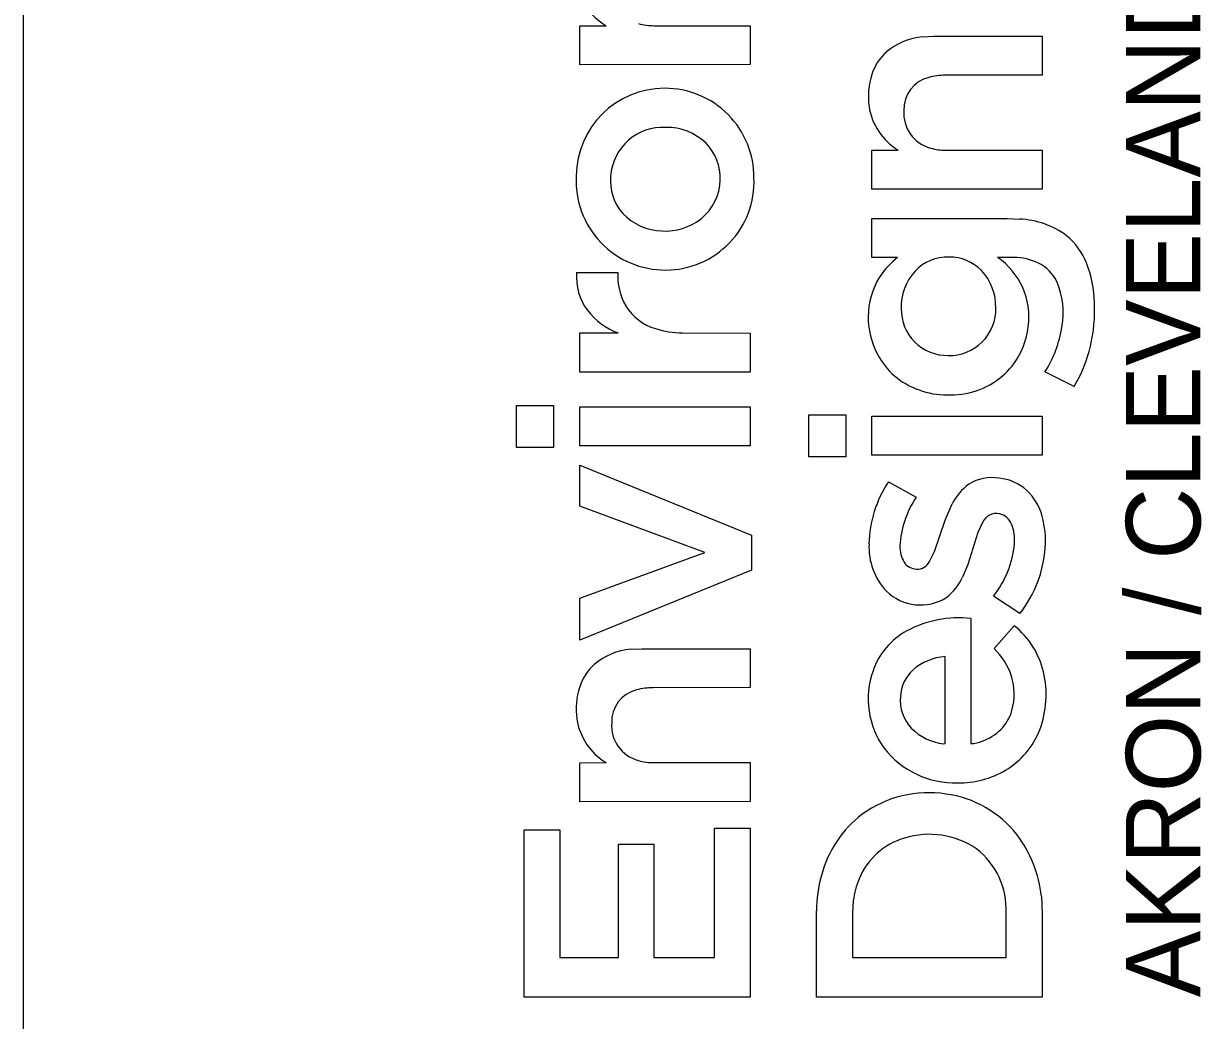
# Model space of a CAD drawing. Extents: x -0.5 to 34, y 0 to 22.
# Drawn here: x 32 to 32.901, y 3.12 to 3.882 of the extents above; entities that cross this region are included whole.
import ezdxf

# ---------------------------------------------------------------- set-up
doc = ezdxf.new("R2010")
doc.units = 0
doc.layers.add('SV_X_Mon_Cells_Found', color=7, linetype='Continuous')
doc.layers.add('SV_X_Shot_Marker', color=7, linetype='Continuous')

msp = doc.modelspace()

# ---------------------------------------------------------------- linework, layer by layer
at = {"layer": 'SV_X_Mon_Cells_Found'}
for p, q in [((32.42542, 3.88066), (32.44552, 3.88071)), ((32.42542, 3.85086), (32.42542, 3.88066)), ((32.48222, 3.88071), (32.55569, 3.88071)), ((32.55569, 3.88071), (32.55571, 3.85096)), ((32.68784, 3.8722), (32.69634, 3.87266)), ((32.69634, 3.87266), (32.77916, 3.87266)), ((32.77916, 3.87266), (32.77917, 3.84287)), ((32.55571, 3.85096), (32.42542, 3.85086)), ((32.77917, 3.84287), (32.70485, 3.8428)), ((32.64888, 3.7855), (32.66897, 3.78555)), ((32.64888, 3.75569), (32.64888, 3.7855)), ((32.70568, 3.78555), (32.77915, 3.78555)), ((32.77915, 3.78555), (32.77917, 3.75579)), ((32.77917, 3.75579), (32.64888, 3.75569)), ((32.6489, 3.70336), (32.64889, 3.73322)), ((32.64889, 3.73322), (32.75236, 3.73322)), ((32.75236, 3.73322), (32.76191, 3.73285)), ((32.66836, 3.70336), (32.6489, 3.70336)), ((32.75763, 3.70356), (32.74487, 3.70361)), ((32.42299, 3.69193), (32.45454, 3.69193)), ((32.42542, 3.64577), (32.45473, 3.64579)), ((32.42542, 3.61593), (32.42542, 3.64577)), ((32.50413, 3.64581), (32.55571, 3.64573)), ((32.55571, 3.64573), (32.55565, 3.61593)), ((32.55565, 3.61593), (32.42542, 3.61593)), ((32.8036, 3.60491), (32.7812, 3.61598)), ((32.37705, 3.55818), (32.37705, 3.59026)), ((32.37705, 3.59026), (32.40543, 3.59026)), ((32.40543, 3.59026), (32.40543, 3.55818)), ((32.42542, 3.55942), (32.42542, 3.58928)), ((32.42542, 3.58928), (32.55571, 3.58928)), ((32.55571, 3.58928), (32.55571, 3.55942)), ((32.60051, 3.55111), (32.60051, 3.58319)), ((32.60051, 3.58319), (32.62889, 3.58319)), ((32.62889, 3.58319), (32.62889, 3.55111)), ((32.64888, 3.55234), (32.64888, 3.5822)), ((32.64888, 3.5822), (32.77917, 3.5822)), ((32.77917, 3.5822), (32.77917, 3.55234)), ((32.55571, 3.55942), (32.42542, 3.55942)), ((32.40543, 3.55818), (32.37705, 3.55818)), ((32.62889, 3.55111), (32.60051, 3.55111)), ((32.77917, 3.55234), (32.64888, 3.55234)), ((32.42542, 3.51327), (32.42542, 3.5446)), ((32.42542, 3.5446), (32.5567, 3.4913)), ((32.66151, 3.53207), (32.68268, 3.52025)), ((32.70483, 3.50258), (32.71036, 3.51526)), ((32.52117, 3.47798), (32.42542, 3.51327)), ((32.69675, 3.47868), (32.70483, 3.50258)), ((32.73342, 3.50101), (32.72985, 3.4933)), ((32.5567, 3.4913), (32.5567, 3.46441)), ((32.72985, 3.4933), (32.72213, 3.46882)), ((32.42542, 3.44294), (32.52117, 3.47798)), ((32.69299, 3.47117), (32.69675, 3.47868)), ((32.72213, 3.46882), (32.71822, 3.45921)), ((32.5567, 3.46441), (32.42542, 3.41086)), ((32.42542, 3.41086), (32.42542, 3.44294)), ((32.76214, 3.43141), (32.74198, 3.44469)), ((32.72453, 3.42747), (32.72463, 3.33195)), ((32.74228, 3.40465), (32.75768, 3.422)), ((32.46439, 3.40397), (32.47289, 3.40443)), ((32.47289, 3.40443), (32.55571, 3.40443)), ((32.55571, 3.40443), (32.55571, 3.37465)), ((32.70489, 3.33182), (32.70489, 3.39834)), ((32.55571, 3.37465), (32.4814, 3.37457)), ((32.70361, 3.33165), (32.70489, 3.33182)), ((32.42542, 3.31728), (32.44552, 3.31733)), ((32.42542, 3.28747), (32.42542, 3.31728)), ((32.48222, 3.31733), (32.55569, 3.31733)), ((32.55569, 3.31733), (32.55571, 3.28756)), ((32.55571, 3.28756), (32.42542, 3.28747)), ((32.38298, 3.13791), (32.38298, 3.26598)), ((32.38298, 3.26598), (32.41012, 3.26598)), ((32.41012, 3.26598), (32.41012, 3.16827)), ((32.52857, 3.16827), (32.52857, 3.26722)), ((32.52857, 3.26722), (32.55571, 3.26722)), ((32.55571, 3.26722), (32.55571, 3.13791)), ((32.45503, 3.16827), (32.45503, 3.25488)), ((32.45503, 3.25488), (32.48218, 3.25488)), ((32.48218, 3.25488), (32.48218, 3.16827)), ((32.63465, 3.21178), (32.63407, 3.2023)), ((32.77847, 3.21497), (32.77917, 3.2021)), ((32.60643, 3.13799), (32.60644, 3.204)), ((32.63407, 3.2023), (32.63407, 3.16838)), ((32.75149, 3.16834), (32.75153, 3.20239)), ((32.77917, 3.2021), (32.77917, 3.138)), ((32.41012, 3.16827), (32.45503, 3.16827)), ((32.48218, 3.16827), (32.52857, 3.16827)), ((32.63407, 3.16838), (32.75149, 3.16834)), ((32.55571, 3.13791), (32.38298, 3.13791)), ((32.77917, 3.138), (32.60643, 3.13799))]:
    msp.add_line(p, q, dxfattribs=at)
for points in [[(32.42542, 3.85086), (32.42542, 3.88066), (32.44552, 3.88071)], [(32.48222, 3.88071), (32.55569, 3.88071), (32.55571, 3.85096), (32.42542, 3.85086)], [(32.68784, 3.8722), (32.69634, 3.87266), (32.77916, 3.87266), (32.77917, 3.84287), (32.70485, 3.8428)], [(32.64888, 3.75569), (32.64888, 3.7855), (32.66897, 3.78555)], [(32.70568, 3.78555), (32.77915, 3.78555), (32.77917, 3.75579), (32.64888, 3.75569)], [(32.66836, 3.70336), (32.6489, 3.70336), (32.64889, 3.73322), (32.75236, 3.73322), (32.76191, 3.73285)], [(32.75763, 3.70356), (32.74487, 3.70361)], [(32.42299, 3.69193), (32.45454, 3.69193)], [(32.50413, 3.64581), (32.55571, 3.64573), (32.55565, 3.61593), (32.42542, 3.61593)], [(32.42542, 3.61593), (32.42542, 3.64577), (32.45473, 3.64579)], [(32.8036, 3.60491), (32.7812, 3.61598)], [(32.66151, 3.53207), (32.68268, 3.52025)], [(32.69299, 3.47117), (32.69675, 3.47868), (32.70483, 3.50258), (32.71036, 3.51526)], [(32.73342, 3.50101), (32.72985, 3.4933), (32.72213, 3.46882), (32.71822, 3.45921)], [(32.76214, 3.43141), (32.74198, 3.44469)], [(32.72453, 3.42747), (32.72463, 3.33195)], [(32.74228, 3.40465), (32.75768, 3.422)], [(32.46439, 3.40397), (32.47289, 3.40443), (32.55571, 3.40443), (32.55571, 3.37465), (32.4814, 3.37457)], [(32.70361, 3.33165), (32.70489, 3.33182), (32.70489, 3.39834)], [(32.42542, 3.28747), (32.42542, 3.31728), (32.44552, 3.31733)], [(32.48222, 3.31733), (32.55569, 3.31733), (32.55571, 3.28756), (32.42542, 3.28747)], [(32.77847, 3.21497), (32.77917, 3.2021), (32.77917, 3.138), (32.60643, 3.13799)], [(32.63465, 3.21178), (32.63407, 3.2023), (32.63407, 3.16838), (32.75149, 3.16834), (32.75153, 3.20239)], [(32.60643, 3.13799), (32.60644, 3.204)]]:
    msp.add_lwpolyline(points, dxfattribs=at)
for points in [[(32.37705, 3.55818), (32.37705, 3.59026), (32.40543, 3.59026), (32.40543, 3.55818)], [(32.42542, 3.55942), (32.42542, 3.58928), (32.55571, 3.58928), (32.55571, 3.55942)], [(32.60051, 3.55111), (32.60051, 3.58319), (32.62889, 3.58319), (32.62889, 3.55111)], [(32.64888, 3.55234), (32.64888, 3.5822), (32.77917, 3.5822), (32.77917, 3.55234)], [(32.42542, 3.41086), (32.42542, 3.44294), (32.52117, 3.47798), (32.42542, 3.51327), (32.42542, 3.5446), (32.5567, 3.4913), (32.5567, 3.46441)], [(32.38298, 3.13791), (32.38298, 3.26598), (32.41012, 3.26598), (32.41012, 3.16827), (32.45503, 3.16827), (32.45503, 3.25488), (32.48218, 3.25488), (32.48218, 3.16827), (32.52857, 3.16827), (32.52857, 3.26722), (32.55571, 3.26722), (32.55571, 3.13791)]]:
    msp.add_lwpolyline(points, close=True, dxfattribs=at)
for centre, radius, start, end in [((32.47027, 3.92141), 0.04763, 188.96462, 238.69865), ((32.47027, 3.92141), 0.04763, 188.96462, 238.69865), ((32.48183, 3.92286), 0.04215, 254.08913, 270.52838), ((32.48183, 3.92286), 0.04215, 254.08913, 270.52838), ((32.69216, 3.82251), 0.04988, 94.97056, 130.22484), ((32.69216, 3.82251), 0.04988, 94.97056, 130.22484), ((32.68694, 3.83085), 0.04016, 132.22383, 161.68229), ((32.68694, 3.83085), 0.04016, 132.22383, 161.68229), ((32.70217, 3.82642), 0.05602, 162.27398, 187.79173), ((32.70217, 3.82642), 0.05602, 162.27398, 187.79173), ((32.69828, 3.81689), 0.02498, 103.68683, 182.21395), ((32.69828, 3.81689), 0.02498, 103.68683, 182.21395), ((32.70453, 3.79679), 0.04601, 89.60515, 105.33026), ((32.70453, 3.79679), 0.04601, 89.60515, 105.33026), ((32.49014, 3.76543), 0.0674, 89.84756, 179.64047), ((32.49014, 3.76543), 0.0674, 89.84756, 179.64047), ((32.49057, 3.76474), 0.0681, 359.54009, 90.21138), ((32.49057, 3.76474), 0.0681, 359.54009, 90.21138), ((32.69372, 3.82624), 0.04763, 188.96462, 238.69865), ((32.69372, 3.82624), 0.04763, 188.96462, 238.69865), ((32.7008, 3.81381), 0.02757, 175.58441, 255.13816), ((32.7008, 3.81381), 0.02757, 175.58441, 255.13816), ((32.48923, 3.76263), 0.0404, 87.04809, 175.57259), ((32.48923, 3.76263), 0.0404, 87.04809, 175.57259), ((32.49204, 3.75999), 0.04299, 45.84264, 90.98008), ((32.49204, 3.75999), 0.04299, 45.84264, 90.98008), ((32.49458, 3.76421), 0.03821, 357.88569, 44.15902), ((32.49458, 3.76421), 0.03821, 357.88569, 44.15902), ((32.70529, 3.82769), 0.04215, 254.08913, 270.52838), ((32.70529, 3.82769), 0.04215, 254.08913, 270.52838), ((32.49083, 3.76209), 0.06819, 176.8344, 270.40384), ((32.49083, 3.76209), 0.06819, 176.8344, 270.40384), ((32.48729, 3.7625), 0.03848, 175.15378, 221.14706), ((32.48729, 3.7625), 0.03848, 175.15378, 221.14706), ((32.49123, 3.76139), 0.06749, 270.06243, 2.37759), ((32.49123, 3.76139), 0.06749, 270.06243, 2.37759), ((32.49446, 3.76318), 0.0383, 308.28936, 359.43468), ((32.49446, 3.76318), 0.0383, 308.28936, 359.43468), ((32.48919, 3.76607), 0.04228, 223.09994, 268.80895), ((32.48919, 3.76607), 0.04228, 223.09994, 268.80895), ((32.49096, 3.7679), 0.04418, 266.56515, 308.06078), ((32.49096, 3.7679), 0.04418, 266.56515, 308.06078), ((32.75907, 3.66789), 0.06503, 53.40344, 87.49062), ((32.75907, 3.66789), 0.06503, 53.40344, 87.49062), ((32.76517, 3.68039), 0.05141, 21.60748, 50.5577), ((32.76517, 3.68039), 0.05141, 21.60748, 50.5577), ((32.70292, 3.65813), 0.05692, 127.37482, 192.22468), ((32.70292, 3.65813), 0.05692, 127.37482, 192.22468), ((32.70693, 3.66927), 0.0346, 88.47302, 136.42562), ((32.70693, 3.66927), 0.0346, 88.47302, 136.42562), ((32.70814, 3.66963), 0.03424, 44.27195, 90.47623), ((32.70814, 3.66963), 0.03424, 44.27195, 90.47623), ((32.71421, 3.65829), 0.05472, 352.1125, 55.92295), ((32.71421, 3.65829), 0.05472, 352.1125, 55.92295), ((32.75666, 3.65725), 0.04633, 65.01687, 88.8011), ((32.75666, 3.65725), 0.04633, 65.01687, 88.8011), ((32.7626, 3.67155), 0.03085, 26.26808, 63.80301), ((32.7626, 3.67155), 0.03085, 26.26808, 63.80301), ((32.73069, 3.66714), 0.08835, 1.15143, 21.3627), ((32.73069, 3.66714), 0.08835, 1.15143, 21.3627), ((32.46616, 3.68882), 0.04329, 175.87313, 216.34747), ((32.46616, 3.68882), 0.04329, 175.87313, 216.34747), ((32.50087, 3.68948), 0.04639, 176.9688, 209.60636), ((32.50087, 3.68948), 0.04639, 176.9688, 209.60636), ((32.71141, 3.66602), 0.0401, 137.46739, 182.33237), ((32.71141, 3.66602), 0.0401, 137.46739, 182.33237), ((32.70368, 3.666), 0.03996, 358.57141, 43.53765), ((32.70368, 3.666), 0.03996, 358.57141, 43.53765), ((32.73565, 3.66154), 0.05953, 349.30734, 23.43071), ((32.73565, 3.66154), 0.05953, 349.30734, 23.43071), ((32.70538, 3.66244), 0.11383, 329.6388, 3.25998), ((32.70538, 3.66244), 0.11383, 329.6388, 3.25998), ((32.47466, 3.69716), 0.05511, 218.09809, 248.7907), ((32.47466, 3.69716), 0.05511, 218.09809, 248.7907), ((32.49514, 3.68814), 0.04079, 211.94466, 253.2028), ((32.49514, 3.68814), 0.04079, 211.94466, 253.2028), ((32.70645, 3.6637), 0.03511, 178.88208, 271.08374), ((32.70645, 3.6637), 0.03511, 178.88208, 271.08374), ((32.70818, 3.66404), 0.03546, 268.27882, 1.55016), ((32.70818, 3.66404), 0.03546, 268.27882, 1.55016), ((32.50465, 3.7165), 0.07069, 252.46555, 269.57296), ((32.50465, 3.7165), 0.07069, 252.46555, 269.57296), ((32.70988, 3.65708), 0.05887, 313.74196, 353.8554), ((32.70988, 3.65708), 0.05887, 313.74196, 353.8554), ((32.70738, 3.66334), 0.08771, 327.31495, 351.57478), ((32.70738, 3.66334), 0.08771, 327.31495, 351.57478), ((32.70463, 3.65696), 0.05837, 190.75182, 231.28919), ((32.70463, 3.65696), 0.05837, 190.75182, 231.28919), ((32.70954, 3.65901), 0.06051, 269.6361, 312.70877), ((32.70954, 3.65901), 0.06051, 269.6361, 312.70877), ((32.70632, 3.66112), 0.06269, 232.46061, 272.59022), ((32.70632, 3.66112), 0.06269, 232.46061, 272.59022), ((32.73636, 3.48258), 0.08973, 146.53104, 178.7571), ((32.73636, 3.48258), 0.08973, 146.53104, 178.7571), ((32.7406, 3.5026), 0.03263, 80.17192, 122.51969), ((32.7406, 3.5026), 0.03263, 80.17192, 122.51969), ((32.74278, 3.49824), 0.03667, 47.79344, 84.68918), ((32.74278, 3.49824), 0.03667, 47.79344, 84.68918), ((32.74661, 3.49713), 0.04053, 125.51182, 153.41595), ((32.74661, 3.49713), 0.04053, 125.51182, 153.41595), ((32.73788, 3.4946), 0.04267, 14.9966, 46.20632), ((32.73788, 3.4946), 0.04267, 14.9966, 46.20632), ((32.74519, 3.4789), 0.07495, 146.51121, 176.91007), ((32.74519, 3.4789), 0.07495, 146.51121, 176.91007), ((32.74384, 3.49631), 0.01143, 76.66094, 155.7053), ((32.74384, 3.49631), 0.01143, 76.66094, 155.7053), ((32.74397, 3.49511), 0.01256, 21.5098, 78.52618), ((32.74397, 3.49511), 0.01256, 21.5098, 78.52618), ((32.71044, 3.48674), 0.07121, 355.83062, 15.39138), ((32.71044, 3.48674), 0.07121, 355.83062, 15.39138), ((32.72592, 3.48766), 0.03209, 354.57264, 22.06805), ((32.72592, 3.48766), 0.03209, 354.57264, 22.06805), ((32.69666, 3.48238), 0.05005, 177.53659, 222.79318), ((32.69666, 3.48238), 0.05005, 177.53659, 222.79318), ((32.6931, 3.48233), 0.02276, 178.47474, 211.08679), ((32.6931, 3.48233), 0.02276, 178.47474, 211.08679), ((32.68248, 3.49149), 0.0757, 321.81101, 354.79685), ((32.68248, 3.49149), 0.0757, 321.81101, 354.79685), ((32.68952, 3.4882), 0.09219, 321.9777, 355.87384), ((32.68952, 3.4882), 0.09219, 321.9777, 355.87384), ((32.68331, 3.4767), 0.01148, 212.23676, 268.37769), ((32.68331, 3.4767), 0.01148, 212.23676, 268.37769), ((32.68342, 3.47589), 0.01067, 267.71603, 333.73375), ((32.68342, 3.47589), 0.01067, 267.71603, 333.73375), ((32.68098, 3.4758), 0.04077, 308.08772, 335.98736), ((32.68098, 3.4758), 0.04077, 308.08772, 335.98736), ((32.68599, 3.47535), 0.0375, 225.98539, 302.47965), ((32.68599, 3.47535), 0.0375, 225.98539, 302.47965), ((32.7152, 3.34414), 0.08384, 83.61499, 118.28755), ((32.7152, 3.34414), 0.08384, 83.61499, 118.28755), ((32.70239, 3.36906), 0.05583, 118.83082, 160.62438), ((32.70239, 3.36906), 0.05583, 118.83082, 160.62438), ((32.71744, 3.37167), 0.06443, 13.53365, 51.36148), ((32.71744, 3.37167), 0.06443, 13.53365, 51.36148), ((32.46871, 3.35428), 0.04988, 94.96958, 130.22249), ((32.46871, 3.35428), 0.04988, 94.96958, 130.22249), ((32.70785, 3.35609), 0.04235, 94.00805, 130.88169), ((32.70785, 3.35609), 0.04235, 94.00805, 130.88169), ((32.70378, 3.36556), 0.05486, 19.03571, 45.44059), ((32.70378, 3.36556), 0.05486, 19.03571, 45.44059), ((32.46348, 3.36263), 0.04015, 132.22192, 161.68183), ((32.46348, 3.36263), 0.04015, 132.22192, 161.68183), ((32.71041, 3.36612), 0.06437, 160.52012, 215.78311), ((32.71041, 3.36612), 0.06437, 160.52012, 215.78311), ((32.70048, 3.36628), 0.02985, 132.98507, 177.179), ((32.70048, 3.36628), 0.02985, 132.98507, 177.179), ((32.71069, 3.3697), 0.047, 344.60586, 17.007), ((32.71069, 3.3697), 0.047, 344.60586, 17.007), ((32.70635, 3.36921), 0.07579, 339.3542, 13.37853), ((32.70635, 3.36921), 0.07579, 339.3542, 13.37853), ((32.47872, 3.35819), 0.05601, 162.27355, 187.79185), ((32.47872, 3.35819), 0.05601, 162.27355, 187.79185), ((32.47482, 3.34867), 0.02498, 103.68646, 182.21874), ((32.47482, 3.34867), 0.02498, 103.68646, 182.21874), ((32.48108, 3.32856), 0.04601, 89.60494, 105.3284), ((32.48108, 3.32856), 0.04601, 89.60494, 105.3284), ((32.7017, 3.36503), 0.03115, 175.00126, 223.28301), ((32.7017, 3.36503), 0.03115, 175.00126, 223.28301), ((32.7224, 3.36715), 0.03504, 288.00773, 343.55078), ((32.7224, 3.36715), 0.03504, 288.00773, 343.55078), ((32.47026, 3.35802), 0.04762, 188.96199, 238.70369), ((32.47026, 3.35802), 0.04762, 188.96199, 238.70369), ((32.47735, 3.34558), 0.02756, 175.58538, 255.14386), ((32.47735, 3.34558), 0.02756, 175.58538, 255.14386), ((32.70891, 3.37363), 0.04231, 225.06188, 262.79738), ((32.70891, 3.37363), 0.04231, 225.06188, 262.79738), ((32.71894, 3.3652), 0.0626, 300.94269, 338.73225), ((32.71894, 3.3652), 0.0626, 300.94269, 338.73225), ((32.72474, 3.35216), 0.02021, 269.7003, 294.8711), ((32.72474, 3.35216), 0.02021, 269.7003, 294.8711), ((32.71253, 3.37054), 0.06872, 217.74516, 271.65431), ((32.71253, 3.37054), 0.06872, 217.74516, 271.65431), ((32.48183, 3.35948), 0.04215, 254.09162, 270.52835), ((32.48183, 3.35948), 0.04215, 254.09162, 270.52835), ((32.71549, 3.37241), 0.07056, 269.20477, 300.33412), ((32.71549, 3.37241), 0.07056, 269.20477, 300.33412), ((32.69229, 3.20792), 0.08641, 81.19402, 125.99844), ((32.69229, 3.20792), 0.08641, 81.19402, 125.99844), ((32.69458, 3.21132), 0.08272, 37.85208, 82.40204), ((32.69458, 3.21132), 0.08272, 37.85208, 82.40204), ((32.69387, 3.20893), 0.08654, 127.23621, 165.14796), ((32.69387, 3.20893), 0.08654, 127.23621, 165.14796), ((32.69279, 3.19862), 0.06389, 55.67272, 107.20935), ((32.69279, 3.19862), 0.06389, 55.67272, 107.20935), ((32.68586, 3.20567), 0.09308, 5.73329, 37.30396), ((32.68586, 3.20567), 0.09308, 5.73329, 37.30396), ((32.68893, 3.20782), 0.05398, 106.18808, 157.38609), ((32.68893, 3.20782), 0.05398, 106.18808, 157.38609), ((32.69291, 3.20499), 0.05867, 357.46616, 52.26647), ((32.69291, 3.20499), 0.05867, 357.46616, 52.26647), ((32.71426, 3.20281), 0.10783, 164.7861, 179.37039), ((32.71426, 3.20281), 0.10783, 164.7861, 179.37039), ((32.69829, 3.20389), 0.06412, 157.35705, 172.92755), ((32.69829, 3.20389), 0.06412, 157.35705, 172.92755)]:
    msp.add_arc(centre, radius, start, end, dxfattribs=at)
at = {"layer": 'SV_X_Shot_Marker'}
msp.add_line((32, 0.5), (32, 21.5), dxfattribs=at)

# ---------------------------------------------------------------- texts
at = {"layer": 'SV_X_Mon_Cells_Found'}
msp.add_text('AKRON / CLEVELAND / COLUMBUS', height=0.056969, rotation=90, dxfattribs=at).set_placement((32.90012, 3.138))

doc.saveas('drawing.dxf')
